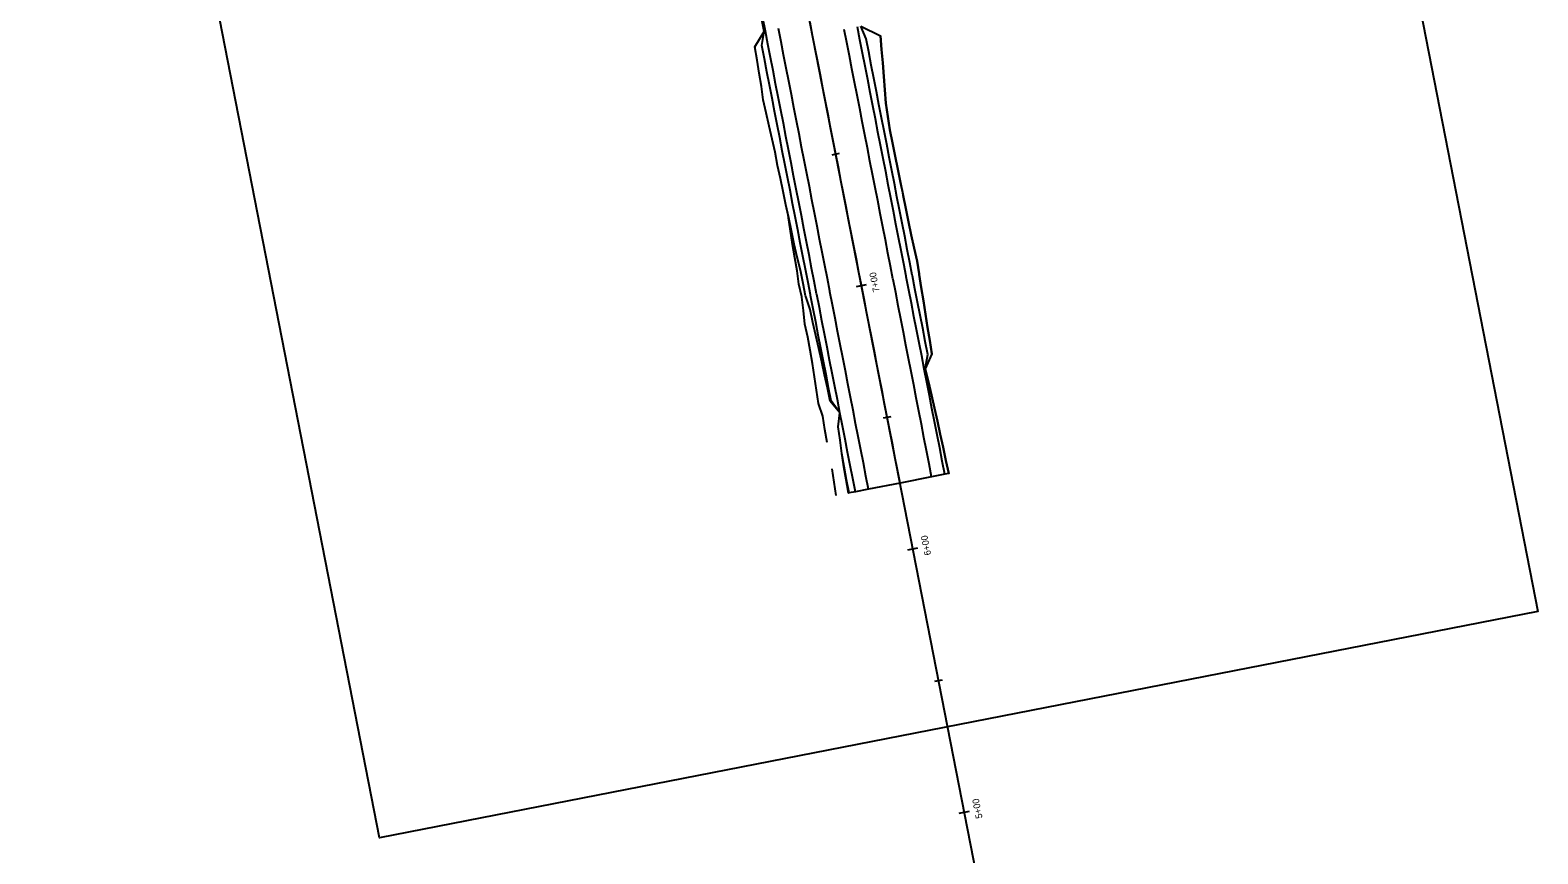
# Model space of a CAD drawing. Extents: x 1150550 to 1151113, y 1141187 to 1143500.
# Drawn here: x 1150550 to 1151113, y 1141479 to 1141786 of the extents above; entities that cross this region are included whole.
import ezdxf

# ---------------------------------------------------------------- set-up
doc = ezdxf.new("R2010")
doc.units = 0
for name, color, linetype in [('AC_P', 7, 'Continuous'), ('ACSR_P_T', 7, 'Continuous'), ('ACSRT_P', 7, 'Continuous'), ('Default', 7, 'Continuous'), ('LELB_P', 7, 'Continuous'), ('LFILL_P', 7, 'Continuous'), ('PE_P', 7, 'Continuous'), ('PET_P', 7, 'Continuous'), ('XSCTOP1_P', 7, 'Continuous')]:
    doc.layers.add(name, color=color, linetype=linetype)

msp = doc.modelspace()

# ---------------------------------------------------------------- linework, layer by layer
at = {"layer": 'AC_P'}
msp.add_line((1150956.27, 1141200.06), (1150819.56, 1141899.84), dxfattribs=at)
msp.add_lwpolyline([(1150874.78, 1141617.18), (1150873.82, 1141622.09), (1150872.87, 1141626.99), (1150871.91, 1141631.9), (1150870.95, 1141636.81), (1150869.99, 1141641.72), (1150869.03, 1141646.62), (1150868.07, 1141651.53), (1150867.11, 1141656.44), (1150866.15, 1141661.35), (1150865.2, 1141666.25), (1150864.24, 1141671.16), (1150863.28, 1141676.07), (1150862.32, 1141680.97), (1150861.36, 1141685.88), (1150860.4, 1141690.79), (1150860.36, 1141691.01), (1150859.44, 1141695.7), (1150858.49, 1141700.6), (1150857.53, 1141705.51), (1150856.57, 1141710.42), (1150855.61, 1141715.32), (1150854.65, 1141720.23), (1150853.69, 1141725.14), (1150852.73, 1141730.05), (1150851.77, 1141734.95), (1150850.82, 1141739.86), (1150849.86, 1141744.77), (1150848.9, 1141749.68), (1150847.94, 1141754.58), (1150846.98, 1141759.49), (1150846.02, 1141764.4), (1150845.06, 1141769.3), (1150844.11, 1141774.21), (1150843.15, 1141779.12), (1150842.19, 1141784.03), (1150841.23, 1141788.93)], dxfattribs=at)
at = {"layer": 'ACSRT_P'}
for points in [[(1150849.4, 1141739.58), (1150852.23, 1141740.14)], [(1150858.52, 1141690.42), (1150862.29, 1141691.16)], [(1150868.58, 1141641.44), (1150871.4, 1141641.99)], [(1150877.69, 1141592.28), (1150881.46, 1141593.01)], [(1150887.75, 1141543.3), (1150890.58, 1141543.85)], [(1150896.86, 1141494.13), (1150900.63, 1141494.87)]]:
    msp.add_lwpolyline(points, dxfattribs=at)
at = {"layer": 'Default'}
msp.add_line((1150956.27, 1141200.06), (1150657.48, 1142729.55), dxfattribs=at)
msp.add_lwpolyline([(1150982.27, 1142236.63), (1151112.58, 1141569.23), (1150680.73, 1141484.91), (1150550.43, 1142152.31)], close=True, dxfattribs=at)
at = {"layer": 'LELB_P'}
for points in [[(1150860.13, 1141787.53), (1150867.47, 1141783.87), (1150867.89, 1141778.86), (1150868.31, 1141773.84), (1150868.71, 1141768.83), (1150869.12, 1141763.81), (1150869.52, 1141758.8), (1150870.18, 1141753.83), (1150871.02, 1141748.9), (1150872.01, 1141744), (1150873, 1141739.1), (1150873.99, 1141734.2), (1150874.97, 1141729.3), (1150875.95, 1141724.39), (1150876.92, 1141719.49), (1150877.89, 1141714.58), (1150878.86, 1141709.68), (1150879.98, 1141704.8), (1150881.1, 1141699.93), (1150881.88, 1141695.21), (1150881.92, 1141694.99), (1150882.7, 1141690.05), (1150883.48, 1141685.11), (1150884.26, 1141680.17), (1150885.05, 1141675.22), (1150885.83, 1141670.28), (1150886.64, 1141665.35), (1150884.19, 1141659.77), (1150885.38, 1141654.91), (1150886.55, 1141650.05), (1150887.64, 1141645.16), (1150888.71, 1141640.28), (1150889.77, 1141635.39), (1150890.82, 1141630.5), (1150891.87, 1141625.61), (1150892.9, 1141620.72), (1150891.47, 1141620.44), (1150886.56, 1141619.48), (1150874.78, 1141617.18), (1150863.01, 1141614.88), (1150858.1, 1141613.92), (1150855.81, 1141613.47), (1150855.51, 1141613.41), (1150854.68, 1141618.35), (1150853.85, 1141623.28), (1150853.11, 1141628.23), (1150852.41, 1141633.19), (1150851.72, 1141638.15), (1150852.3, 1141643.35), (1150848.71, 1141647.75), (1150847.67, 1141652.64), (1150846.62, 1141657.53), (1150845.55, 1141662.41), (1150844.47, 1141667.3), (1150843.38, 1141672.18), (1150842.29, 1141677.06), (1150841.2, 1141681.94), (1150839.61, 1141686.73), (1150839.57, 1141686.95), (1150838.68, 1141691.64), (1150837.69, 1141696.54), (1150836.41, 1141701.38), (1150835.33, 1141706.27), (1150834.29, 1141711.16), (1150833.25, 1141716.05), (1150832.22, 1141720.94), (1150831.19, 1141725.84), (1150830.17, 1141730.73), (1150829.13, 1141735.63), (1150828.15, 1141740.53), (1150827.04, 1141745.41), (1150825.93, 1141750.28), (1150824.83, 1141755.16), (1150823.77, 1141760.05), (1150823.09, 1141765.01), (1150822.28, 1141769.95), (1150821.47, 1141774.88), (1150820.67, 1141779.82), (1150824.11, 1141785.59), (1150823.14, 1141790.49)], [(1150892.9, 1141620.72), (1150891.87, 1141625.61), (1150890.82, 1141630.5), (1150889.77, 1141635.39), (1150888.71, 1141640.28), (1150887.64, 1141645.16), (1150886.55, 1141650.05), (1150885.38, 1141654.91), (1150884.19, 1141659.77), (1150885.13, 1141665.05), (1150884.17, 1141669.96), (1150883.21, 1141674.87), (1150882.25, 1141679.77), (1150881.29, 1141684.68), (1150880.34, 1141689.59), (1150879.38, 1141694.5), (1150879.33, 1141694.71), (1150878.42, 1141699.4), (1150877.46, 1141704.31), (1150876.5, 1141709.22), (1150875.54, 1141714.12), (1150874.58, 1141719.03), (1150873.63, 1141723.94), (1150872.67, 1141728.85), (1150871.71, 1141733.75), (1150870.75, 1141738.66), (1150869.79, 1141743.57), (1150868.83, 1141748.47), (1150867.87, 1141753.38), (1150866.91, 1141758.29), (1150865.96, 1141763.2), (1150865, 1141768.1), (1150864.04, 1141773.01), (1150863.08, 1141777.92), (1150862.12, 1141782.83), (1150860.13, 1141787.53)], [(1150855.81, 1141613.47), (1150854.85, 1141618.38), (1150853.89, 1141623.29), (1150853.11, 1141628.23), (1150852.41, 1141633.19), (1150851.72, 1141638.15), (1150852.3, 1141643.35), (1150849.1, 1141647.82), (1150848.14, 1141652.73), (1150847.18, 1141657.64), (1150846.22, 1141662.55), (1150845.26, 1141667.45), (1150844.3, 1141672.36), (1150843.35, 1141677.27), (1150842.39, 1141682.17), (1150841.43, 1141687.08), (1150841.39, 1141687.3), (1150840.47, 1141691.99), (1150839.51, 1141696.9), (1150838.55, 1141701.8), (1150837.59, 1141706.71), (1150836.63, 1141711.62), (1150835.68, 1141716.53), (1150834.72, 1141721.43), (1150833.76, 1141726.34), (1150832.8, 1141731.25), (1150831.84, 1141736.15), (1150830.88, 1141741.06), (1150829.92, 1141745.97), (1150828.97, 1141750.88), (1150828.01, 1141755.78), (1150827.05, 1141760.69), (1150826.09, 1141765.6), (1150825.13, 1141770.5), (1150824.17, 1141775.41), (1150823.21, 1141780.32), (1150824.11, 1141785.59)]]:
    msp.add_lwpolyline(points, dxfattribs=at)
at = {"layer": 'LFILL_P'}
for points in [[(1150886.64, 1141665.35), (1150885.83, 1141670.28), (1150885.05, 1141675.22), (1150884.26, 1141680.17), (1150883.48, 1141685.11), (1150882.7, 1141690.05), (1150881.92, 1141694.99), (1150881.88, 1141695.21), (1150881.1, 1141699.93), (1150879.98, 1141704.8), (1150878.86, 1141709.68), (1150877.89, 1141714.58), (1150876.92, 1141719.49), (1150875.95, 1141724.39), (1150875.75, 1141725.37), (1150874.97, 1141729.3), (1150873.99, 1141734.2), (1150873, 1141739.1), (1150872.01, 1141744), (1150871.02, 1141748.9), (1150870.18, 1141753.83), (1150869.52, 1141758.8), (1150869.12, 1141763.81), (1150868.71, 1141768.83), (1150868.31, 1141773.84), (1150867.89, 1141778.86), (1150867.47, 1141783.87)], [(1150847.63, 1141632.25), (1150846.71, 1141637.17), (1150846.03, 1141642.13), (1150844.33, 1141646.89), (1150843.6, 1141651.84), (1150842.85, 1141656.79), (1150842.08, 1141661.74), (1150841.24, 1141666.67), (1150840.39, 1141671.59), (1150839.27, 1141676.47), (1150838.73, 1141681.46), (1150838.13, 1141686.44), (1150838.09, 1141686.66), (1150837.07, 1141691.33), (1150836.43, 1141696.29), (1150835.48, 1141701.2), (1150834.71, 1141706.15), (1150833.95, 1141711.09), (1150833.2, 1141716.04), (1150833.04, 1141717.03), (1150832.22, 1141720.94), (1150831.19, 1141725.84), (1150830.17, 1141730.73), (1150829.13, 1141735.63), (1150828.15, 1141740.53), (1150827.04, 1141745.41), (1150825.93, 1141750.28), (1150824.83, 1141755.16), (1150823.77, 1141760.05), (1150823.09, 1141765.01), (1150822.28, 1141769.95), (1150821.47, 1141774.88), (1150820.67, 1141779.82)], [(1150851.01, 1141612.54), (1150850.19, 1141617.47), (1150849.5, 1141622.43)]]:
    msp.add_lwpolyline(points, dxfattribs=at)
at = {"layer": 'PE_P'}
for points in [[(1150858.1, 1141613.92), (1150857.14, 1141618.83), (1150856.18, 1141623.73), (1150855.22, 1141628.64), (1150854.26, 1141633.55), (1150853.3, 1141638.46), (1150852.35, 1141643.36), (1150851.39, 1141648.27), (1150850.43, 1141653.18), (1150849.47, 1141658.09), (1150848.51, 1141662.99), (1150847.55, 1141667.9), (1150846.59, 1141672.81), (1150845.64, 1141677.71), (1150844.68, 1141682.62), (1150843.72, 1141687.53), (1150843.68, 1141687.75), (1150842.76, 1141692.44), (1150841.8, 1141697.34), (1150840.84, 1141702.25), (1150839.88, 1141707.16), (1150838.92, 1141712.07), (1150837.97, 1141716.97), (1150837.01, 1141721.88), (1150836.05, 1141726.79), (1150835.09, 1141731.69), (1150834.13, 1141736.6), (1150833.17, 1141741.51), (1150832.21, 1141746.42), (1150831.26, 1141751.32), (1150830.3, 1141756.23), (1150829.34, 1141761.14), (1150828.38, 1141766.04), (1150827.42, 1141770.95), (1150826.46, 1141775.86), (1150825.5, 1141780.77), (1150824.55, 1141785.67), (1150823.59, 1141790.58)], [(1150891.47, 1141620.44), (1150890.51, 1141625.35), (1150889.55, 1141630.25), (1150888.59, 1141635.16), (1150887.63, 1141640.07), (1150886.67, 1141644.98), (1150885.72, 1141649.88), (1150884.76, 1141654.79), (1150883.8, 1141659.7), (1150882.84, 1141664.6), (1150881.88, 1141669.51), (1150880.92, 1141674.42), (1150879.96, 1141679.33), (1150879, 1141684.23), (1150878.05, 1141689.14), (1150877.09, 1141694.05), (1150877.04, 1141694.27), (1150876.13, 1141698.96), (1150875.17, 1141703.86), (1150874.21, 1141708.77), (1150873.25, 1141713.68), (1150872.29, 1141718.58), (1150871.34, 1141723.49), (1150870.38, 1141728.4), (1150869.42, 1141733.31), (1150868.46, 1141738.21), (1150867.5, 1141743.12), (1150866.54, 1141748.03), (1150865.58, 1141752.93), (1150864.62, 1141757.84), (1150863.67, 1141762.75), (1150862.71, 1141767.66), (1150861.75, 1141772.56), (1150860.79, 1141777.47), (1150859.83, 1141782.38), (1150858.87, 1141787.29)]]:
    msp.add_lwpolyline(points, dxfattribs=at)
at = {"layer": 'PET_P'}
for points in [[(1150863.01, 1141614.88), (1150862.05, 1141619.79), (1150861.09, 1141624.69), (1150860.13, 1141629.6), (1150859.17, 1141634.51), (1150858.21, 1141639.42), (1150857.25, 1141644.32), (1150856.29, 1141649.23), (1150855.34, 1141654.14), (1150854.38, 1141659.04), (1150853.42, 1141663.95), (1150852.46, 1141668.86), (1150851.5, 1141673.77), (1150850.54, 1141678.67), (1150849.58, 1141683.58), (1150848.63, 1141688.49), (1150848.58, 1141688.71), (1150847.67, 1141693.39), (1150846.71, 1141698.3), (1150845.75, 1141703.21), (1150844.79, 1141708.12), (1150843.83, 1141713.02), (1150842.87, 1141717.93), (1150841.91, 1141722.84), (1150840.96, 1141727.75), (1150840, 1141732.65), (1150839.04, 1141737.56), (1150838.08, 1141742.47), (1150837.12, 1141747.37), (1150836.16, 1141752.28), (1150835.2, 1141757.19), (1150834.25, 1141762.1), (1150833.29, 1141767), (1150832.33, 1141771.91), (1150831.37, 1141776.82), (1150830.41, 1141781.73), (1150829.45, 1141786.63)], [(1150886.56, 1141619.48), (1150885.6, 1141624.39), (1150884.64, 1141629.3), (1150883.68, 1141634.2), (1150882.73, 1141639.11), (1150881.77, 1141644.02), (1150880.81, 1141648.92), (1150879.85, 1141653.83), (1150878.89, 1141658.74), (1150877.93, 1141663.65), (1150876.97, 1141668.55), (1150876.01, 1141673.46), (1150875.06, 1141678.37), (1150874.1, 1141683.27), (1150873.14, 1141688.18), (1150872.18, 1141693.09), (1150872.14, 1141693.31), (1150871.22, 1141698), (1150870.26, 1141702.9), (1150869.3, 1141707.81), (1150868.35, 1141712.72), (1150867.39, 1141717.63), (1150866.43, 1141722.53), (1150865.47, 1141727.44), (1150864.51, 1141732.35), (1150863.55, 1141737.25), (1150862.59, 1141742.16), (1150861.63, 1141747.07), (1150860.68, 1141751.98), (1150859.72, 1141756.88), (1150858.76, 1141761.79), (1150857.8, 1141766.7), (1150856.84, 1141771.61), (1150855.88, 1141776.51), (1150854.92, 1141781.42), (1150853.97, 1141786.33)]]:
    msp.add_lwpolyline(points, dxfattribs=at)
at = {"layer": 'XSCTOP1_P'}
for points in [[(1150858.1, 1141613.92), (1150857.14, 1141618.83), (1150856.18, 1141623.73), (1150855.22, 1141628.64), (1150854.26, 1141633.55), (1150853.3, 1141638.46), (1150852.35, 1141643.36), (1150851.39, 1141648.27), (1150850.43, 1141653.18), (1150849.47, 1141658.09), (1150848.51, 1141662.99), (1150847.55, 1141667.9), (1150846.59, 1141672.81), (1150845.64, 1141677.71), (1150844.68, 1141682.62), (1150843.72, 1141687.53), (1150843.68, 1141687.75), (1150842.76, 1141692.44), (1150841.8, 1141697.34), (1150840.84, 1141702.25), (1150839.88, 1141707.16), (1150838.92, 1141712.07), (1150837.97, 1141716.97), (1150837.01, 1141721.88), (1150836.05, 1141726.79), (1150835.09, 1141731.69), (1150834.13, 1141736.6), (1150833.17, 1141741.51), (1150832.21, 1141746.42), (1150831.26, 1141751.32), (1150830.3, 1141756.23), (1150829.34, 1141761.14), (1150828.38, 1141766.04), (1150827.42, 1141770.95), (1150826.46, 1141775.86), (1150825.5, 1141780.77), (1150824.55, 1141785.67), (1150823.59, 1141790.58)], [(1150863.01, 1141614.88), (1150862.05, 1141619.79), (1150861.09, 1141624.69), (1150860.13, 1141629.6), (1150859.17, 1141634.51), (1150858.21, 1141639.42), (1150857.25, 1141644.32), (1150856.29, 1141649.23), (1150855.34, 1141654.14), (1150854.38, 1141659.04), (1150853.42, 1141663.95), (1150852.46, 1141668.86), (1150851.5, 1141673.77), (1150850.54, 1141678.67), (1150849.58, 1141683.58), (1150848.63, 1141688.49), (1150848.58, 1141688.71), (1150847.67, 1141693.39), (1150846.71, 1141698.3), (1150845.75, 1141703.21), (1150844.79, 1141708.12), (1150843.83, 1141713.02), (1150842.87, 1141717.93), (1150841.91, 1141722.84), (1150840.96, 1141727.75), (1150840, 1141732.65), (1150839.04, 1141737.56), (1150838.08, 1141742.47), (1150837.12, 1141747.37), (1150836.16, 1141752.28), (1150835.2, 1141757.19), (1150834.25, 1141762.1), (1150833.29, 1141767), (1150832.33, 1141771.91), (1150831.37, 1141776.82), (1150830.41, 1141781.73), (1150829.45, 1141786.63)], [(1150874.78, 1141617.18), (1150873.82, 1141622.09), (1150872.87, 1141626.99), (1150871.91, 1141631.9), (1150870.95, 1141636.81), (1150869.99, 1141641.72), (1150869.03, 1141646.62), (1150868.07, 1141651.53), (1150867.11, 1141656.44), (1150866.15, 1141661.35), (1150865.2, 1141666.25), (1150864.24, 1141671.16), (1150863.28, 1141676.07), (1150862.32, 1141680.97), (1150861.36, 1141685.88), (1150860.4, 1141690.79), (1150860.36, 1141691.01), (1150859.44, 1141695.7), (1150858.49, 1141700.6), (1150857.53, 1141705.51), (1150856.57, 1141710.42), (1150855.61, 1141715.32), (1150854.65, 1141720.23), (1150853.69, 1141725.14), (1150852.73, 1141730.05), (1150851.77, 1141734.95), (1150850.82, 1141739.86), (1150849.86, 1141744.77), (1150848.9, 1141749.68), (1150847.94, 1141754.58), (1150846.98, 1141759.49), (1150846.02, 1141764.4), (1150845.06, 1141769.3), (1150844.11, 1141774.21), (1150843.15, 1141779.12), (1150842.19, 1141784.03), (1150841.23, 1141788.93)], [(1150886.56, 1141619.48), (1150885.6, 1141624.39), (1150884.64, 1141629.3), (1150883.68, 1141634.2), (1150882.73, 1141639.11), (1150881.77, 1141644.02), (1150880.81, 1141648.92), (1150879.85, 1141653.83), (1150878.89, 1141658.74), (1150877.93, 1141663.65), (1150876.97, 1141668.55), (1150876.01, 1141673.46), (1150875.06, 1141678.37), (1150874.1, 1141683.27), (1150873.14, 1141688.18), (1150872.18, 1141693.09), (1150872.14, 1141693.31), (1150871.22, 1141698), (1150870.26, 1141702.9), (1150869.3, 1141707.81), (1150868.35, 1141712.72), (1150867.39, 1141717.63), (1150866.43, 1141722.53), (1150865.47, 1141727.44), (1150864.51, 1141732.35), (1150863.55, 1141737.25), (1150862.59, 1141742.16), (1150861.63, 1141747.07), (1150860.68, 1141751.98), (1150859.72, 1141756.88), (1150858.76, 1141761.79), (1150857.8, 1141766.7), (1150856.84, 1141771.61), (1150855.88, 1141776.51), (1150854.92, 1141781.42), (1150853.97, 1141786.33)], [(1150891.47, 1141620.44), (1150890.51, 1141625.35), (1150889.55, 1141630.25), (1150888.59, 1141635.16), (1150887.63, 1141640.07), (1150886.67, 1141644.98), (1150885.72, 1141649.88), (1150884.76, 1141654.79), (1150883.8, 1141659.7), (1150882.84, 1141664.6), (1150881.88, 1141669.51), (1150880.92, 1141674.42), (1150879.96, 1141679.33), (1150879, 1141684.23), (1150878.05, 1141689.14), (1150877.09, 1141694.05), (1150877.04, 1141694.27), (1150876.13, 1141698.96), (1150875.17, 1141703.86), (1150874.21, 1141708.77), (1150873.25, 1141713.68), (1150872.29, 1141718.58), (1150871.34, 1141723.49), (1150870.38, 1141728.4), (1150869.42, 1141733.31), (1150868.46, 1141738.21), (1150867.5, 1141743.12), (1150866.54, 1141748.03), (1150865.58, 1141752.93), (1150864.62, 1141757.84), (1150863.67, 1141762.75), (1150862.71, 1141767.66), (1150861.75, 1141772.56), (1150860.79, 1141777.47), (1150859.83, 1141782.38), (1150858.87, 1141787.29)]]:
    msp.add_lwpolyline(points, dxfattribs=at)

# ---------------------------------------------------------------- texts
at = {"layer": 'ACSR_P_T'}
for s, p in [('7+00', (1150867.2, 1141688.59)), ('6+00', (1150886.37, 1141590.47)), ('5+00', (1150905.54, 1141492.31))]:
    msp.add_text(s, height=2.501, rotation=101.0539, dxfattribs=at).set_placement(p)

doc.saveas('drawing.dxf')
